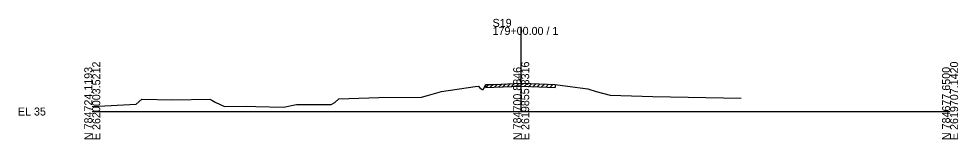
# Model space of a CAD drawing. Extents: x -26 to 1603, y -10 to 5028.
# Drawn here: x -25.7 to 302.8, y 3990.3 to 4032.5 of the extents above; entities that cross this region are included whole.
import ezdxf

# ---------------------------------------------------------------- set-up
doc = ezdxf.new("R2010")
doc.units = 0
for name, color, linetype in [('RD_GPK_XS_Cell', 7, 'Continuous'), ('RD_XS_ExGround', 7, 'Continuous'), ('RD_XS_ExPaveRet', 7, 'Continuous'), ('RD_XS_TX_Elev_EX', 7, 'Continuous')]:
    doc.layers.add(name, color=color, linetype=linetype)

msp = doc.modelspace()

# ---------------------------------------------------------------- linework, layer by layer
at = {"layer": 'RD_GPK_XS_Cell'}
for p, q in [((150, 4000), (150, 4029.61)), ((0, 4000), (150, 4000)), ((150, 4000), (300, 4000))]:
    msp.add_line(p, q, dxfattribs=at)
at = {"layer": 'RD_XS_ExGround'}
for p, q in [((122.09, 4007.05), (133.93, 4008.76)), ((133.93, 4008.76), (135.13, 4008.89)), ((135.13, 4008.89), (135.37, 4008.45)), ((135.37, 4008.45), (136.33, 4007.67)), ((136.72, 4007.76), (137.64, 4009.42)), ((137.64, 4009.42), (140.53, 4009.51)), ((140.53, 4009.51), (149.93, 4009.87)), ((149.93, 4009.87), (153.43, 4009.75)), ((153.43, 4009.75), (161.93, 4009.43)), ((161.93, 4009.43), (166.25, 4008.92)), ((166.25, 4008.92), (173.26, 4007.94)), ((86.26, 4004.49), (100.18, 4004.86)), ((100.18, 4004.86), (115.18, 4005.02)), ((115.18, 4005.02), (117.19, 4005.65)), ((117.19, 4005.65), (122.09, 4007.05)), ((136.33, 4007.67), (136.72, 4007.76)), ((173.26, 4007.94), (176.28, 4007.01)), ((176.28, 4007.01), (181.16, 4005.68)), ((181.16, 4005.68), (196.08, 4005.28)), ((196.08, 4005.28), (226.99, 4004.64)), ((0, 4001.75), (15.37, 4002.6)), ((15.37, 4002.6), (17.33, 4004.37)), ((17.33, 4004.37), (28.23, 4004.1)), ((28.23, 4004.1), (41.12, 4004.29)), ((41.12, 4004.29), (41.77, 4004.02)), ((41.77, 4004.02), (43.04, 4003.32)), ((43.04, 4003.32), (46.22, 4001.79)), ((46.22, 4001.79), (53.92, 4001.84)), ((53.92, 4001.84), (57.16, 4001.75)), ((57.16, 4001.75), (66.93, 4001.49)), ((66.93, 4001.49), (71.42, 4002.44)), ((71.42, 4002.44), (79.56, 4002.44)), ((79.56, 4002.44), (83.56, 4002.43)), ((83.56, 4002.43), (84.81, 4003.17)), ((84.81, 4003.17), (86.26, 4004.49))]:
    msp.add_line(p, q, dxfattribs=at)
at = {"layer": 'RD_XS_ExPaveRet'}
for p, q in [((137.64, 4008.42), (138.68, 4009.45)), ((137.64, 4008.42), (137.64, 4009.42)), ((137.64, 4008.42), (140.53, 4008.51)), ((139.14, 4008.47), (140.18, 4009.5)), ((140.53, 4008.51), (149.93, 4008.87)), ((140.64, 4008.52), (141.68, 4009.56)), ((142.14, 4008.58), (143.18, 4009.61)), ((143.64, 4008.63), (144.68, 4009.67)), ((145.14, 4008.69), (146.18, 4009.73)), ((146.64, 4008.75), (147.68, 4009.78)), ((148.14, 4008.8), (149.18, 4009.84)), ((149.64, 4008.86), (150.63, 4009.85)), ((149.93, 4008.87), (153.43, 4008.75)), ((151.14, 4008.83), (152.11, 4009.79)), ((152.64, 4008.78), (153.61, 4009.74)), ((153.43, 4008.75), (161.93, 4008.43)), ((154.14, 4008.72), (155.11, 4009.69)), ((155.64, 4008.67), (156.61, 4009.63)), ((157.14, 4008.61), (158.11, 4009.58)), ((158.64, 4008.56), (159.61, 4009.52)), ((160.14, 4008.5), (161.11, 4009.46)), ((161.93, 4009.43), (161.93, 4008.43))]:
    msp.add_line(p, q, dxfattribs=at)

# ---------------------------------------------------------------- texts
at = {"layer": 'RD_GPK_XS_Cell'}
for s, p in [('S19', (140, 4029.61)), ('179+00.00 / 1', (140, 4026.81)), ('EL 35', (-26, 3998.6))]:
    msp.add_text(s, height=2.8, dxfattribs=at).set_placement(p)
for s, p in [('N 784724.1193', (0, 3990)), ('E 2620003.5212', (2.8, 3990)), ('N 784700.8846', (150, 3990)), ('E 2619855.3316', (152.8, 3990)), ('N 784677.6500', (300, 3990)), ('E 2619707.1420', (302.8, 3990))]:
    msp.add_text(s, height=2.8, rotation=90, dxfattribs=at).set_placement(p)
at = {"layer": 'RD_XS_TX_Elev_EX'}
msp.add_text('44.87', height=0.8, rotation=90, dxfattribs=at).set_placement((149.9, 4010.31))

doc.saveas('drawing.dxf')
